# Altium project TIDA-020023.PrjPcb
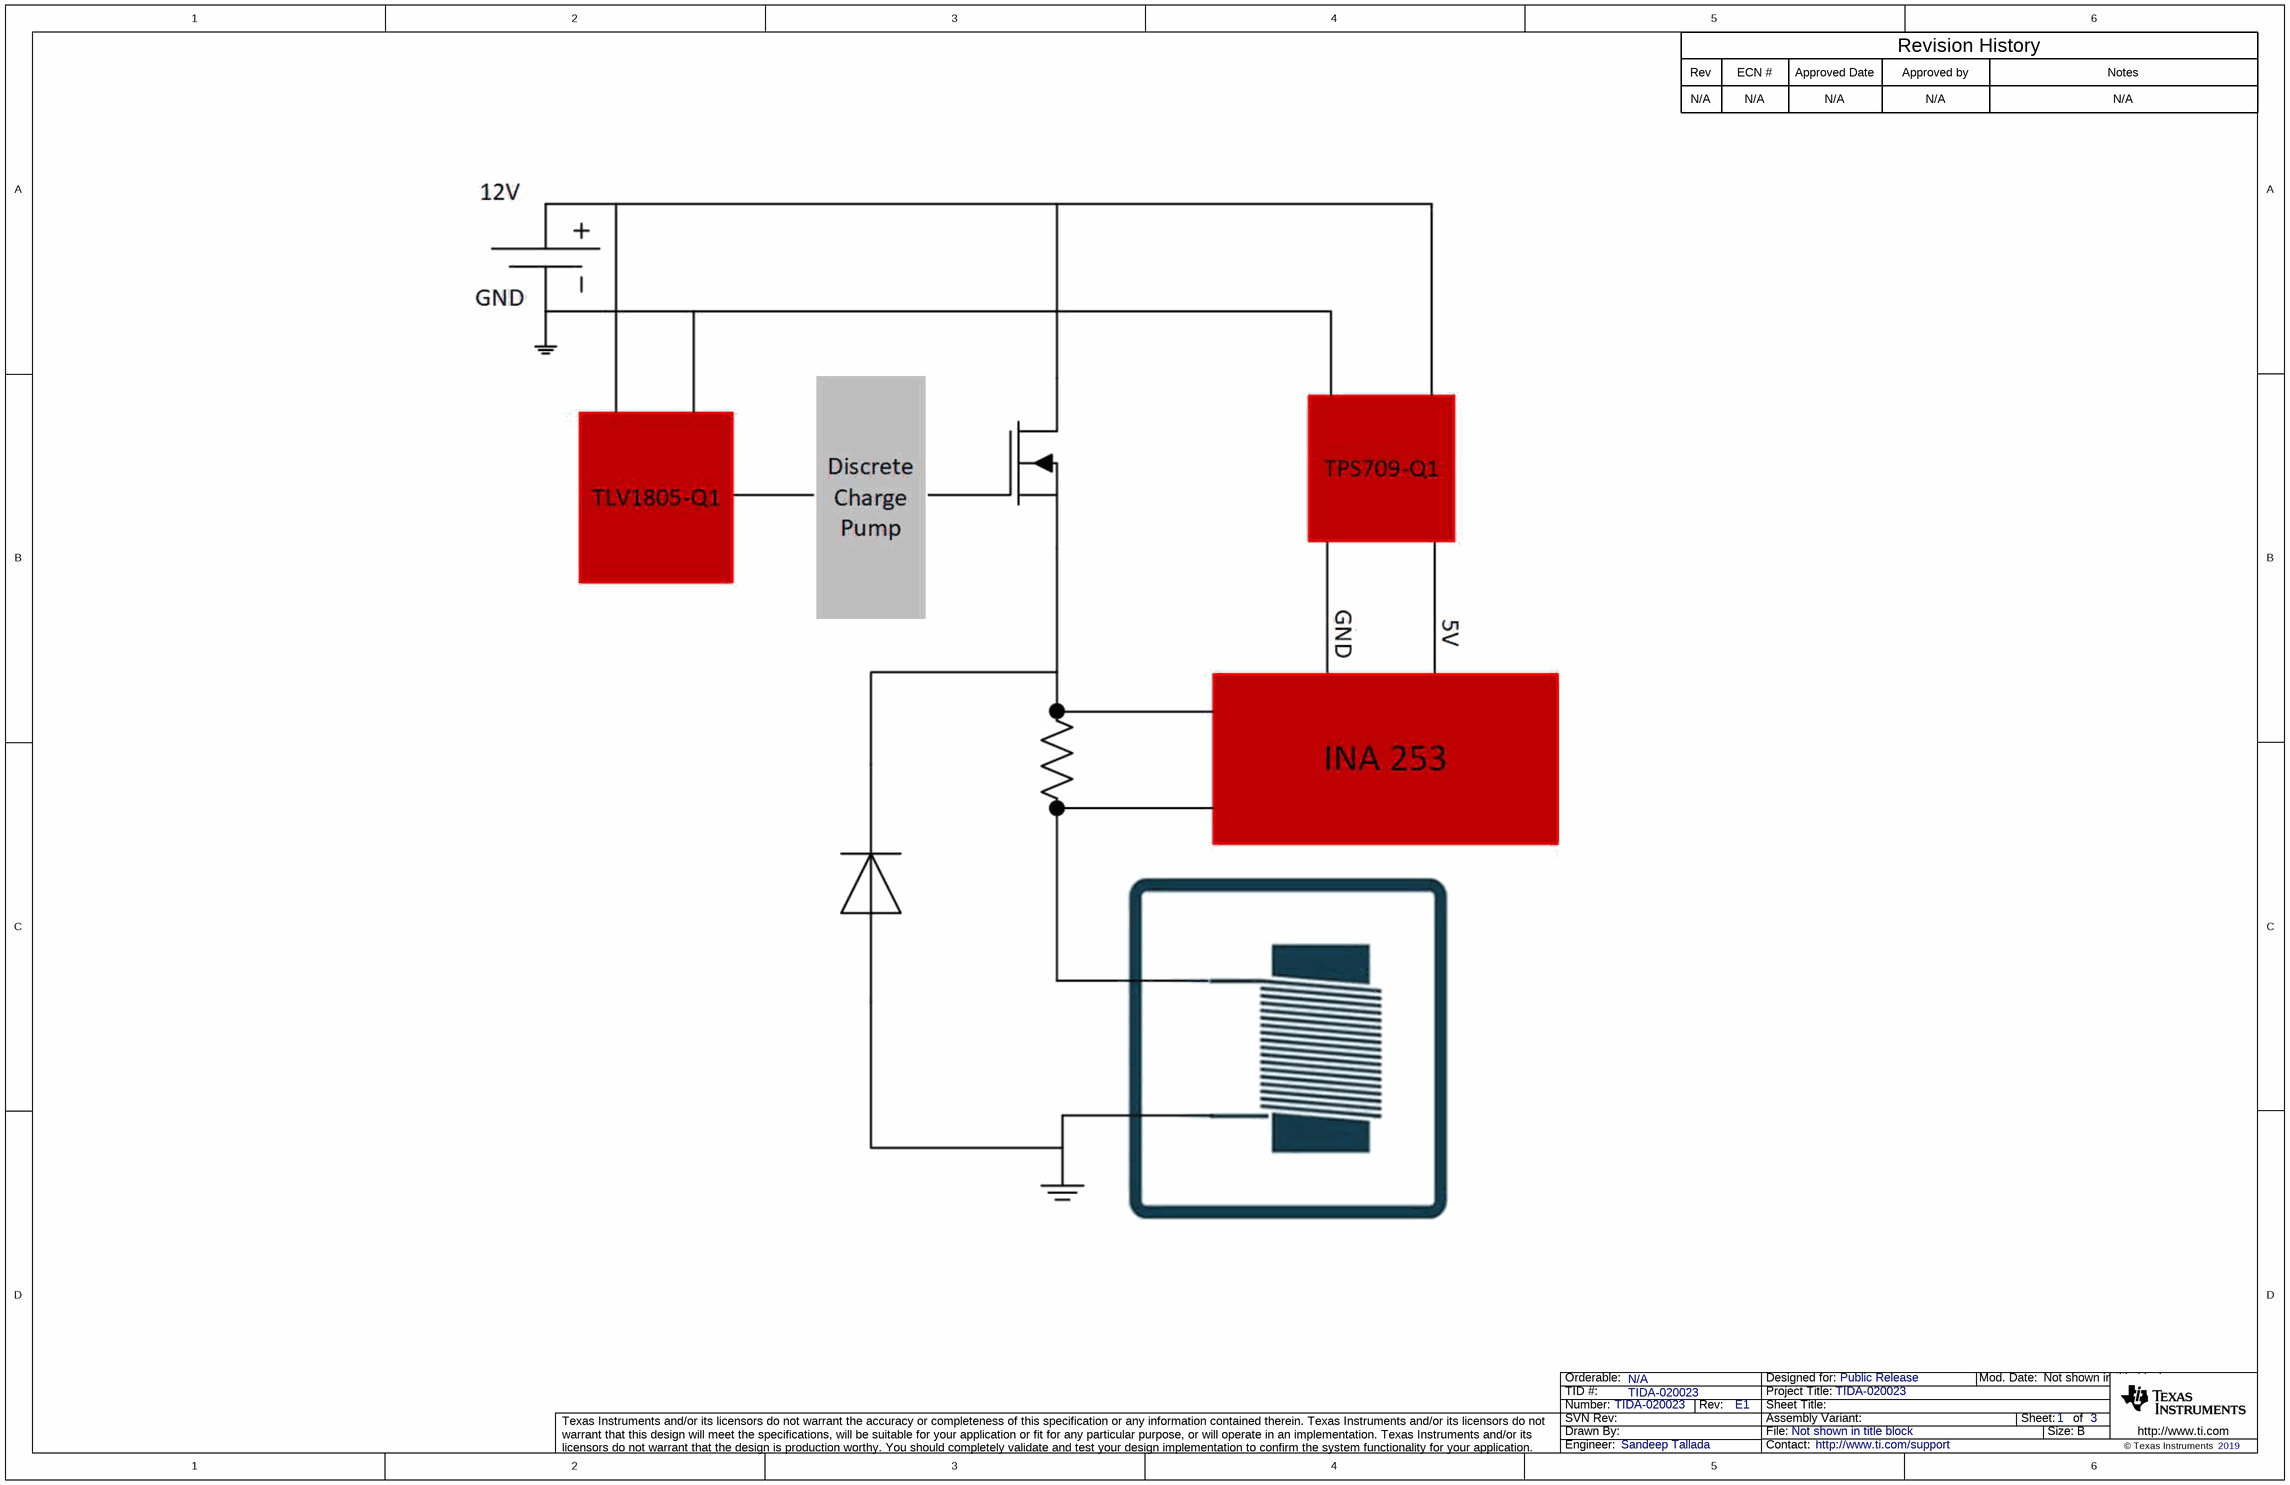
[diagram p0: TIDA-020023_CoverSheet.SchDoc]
CopyrightYear: 2019; EVM_orderable: N/A; PCB_Layout: Sandeep Tallada; PCB_Rev: E1; PRJ_Customer: Public Release; PRJ_Engineer: Sandeep Tallada; PRJ_Number: TIDA-020023; PRJ_Title: TIDA-020023; SCH_Rev: E1; TechSupport: http://www.ti.com/support; TID: TIDA-020023
3 sheets, 39 parts. Net scope: flat (ports and power ports of the same name join across sheets).
Board file: TIDA-020023_PCBLayout.PcbDoc
Sheets:
  TIDA-020023_CoverSheet.SchDoc
  TIDA-020023_Schematics.SchDoc
  TIDA-020023_EVM_Hardware.SchDoc

## Sheet TIDA-020023_CoverSheet.SchDoc
size 431 x 279 mm; Date: Not shown in title block; ApprovedBy: Not shown in title block; CheckedBy: Not shown in title block; Author: Not shown in title block; CompanyName: Not shown in title block; Engineer: Not shown in title block; Organization: Not shown in title block; Address1: Not shown in title block; Address2: Not shown in title block; Address3: Not shown in title block; Address4: Not shown in title block; DocumentNumber: 1; Revision: Use project parameter SCH_Rev; SheetNumber: 1; SheetTotal: 3; PageSetup: Record=PageOptions¦CenterHorizontal=True¦CenterVertical=True¦PrintScale=1.00¦XCorrection=1.00¦YCorrection=1.00¦PrintKind=0¦BorderSize=5000000¦LeftOffset=0¦BottomOffset=0¦Orientation=2¦PaperLength=1000¦PaperWidth=1000¦Scale=100¦PaperSource=15¦PrintQuality=600¦MediaType=1¦DitherType=10¦PaperKind=Letter¦PrintScaleMode=1

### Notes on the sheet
- Rev
- N/A
- ECN #
- Approved Date
- Approved by
- Revision History
- Notes

## Sheet TIDA-020023_Schematics.SchDoc
size 431 x 279 mm; Date: Not shown in title block; ApprovedBy: Not shown in title block; CheckedBy: Not shown in title block; Author: Not shown in title block; CompanyName: Not shown in title block; DrawnBy: Sandeep Tallada; Engineer: Sandeep Tallada; Organization: Not shown in title block; Address1: Not shown in title block; Address2: Not shown in title block; Address3: Not shown in title block; Address4: Not shown in title block; DocumentNumber: 1; Revision: Use project parameter SCH_Rev; SheetNumber: 2; SheetTotal: 3; PageSetup: Record=PageOptions¦CenterHorizontal=True¦CenterVertical=True¦PrintScale=0.62¦XCorrection=1.00¦YCorrection=1.00¦PrintKind=0¦BorderSize=5000000¦LeftOffset=0¦BottomOffset=0¦Orientation=2¦PaperLength=2794¦PaperWidth=2159¦Scale=100¦PaperSource=7¦PrintQuality=600¦MediaType=1¦DitherType=10¦PrintScaleMode=1¦PaperKind=8 1/2x11¦PaperIndex=1
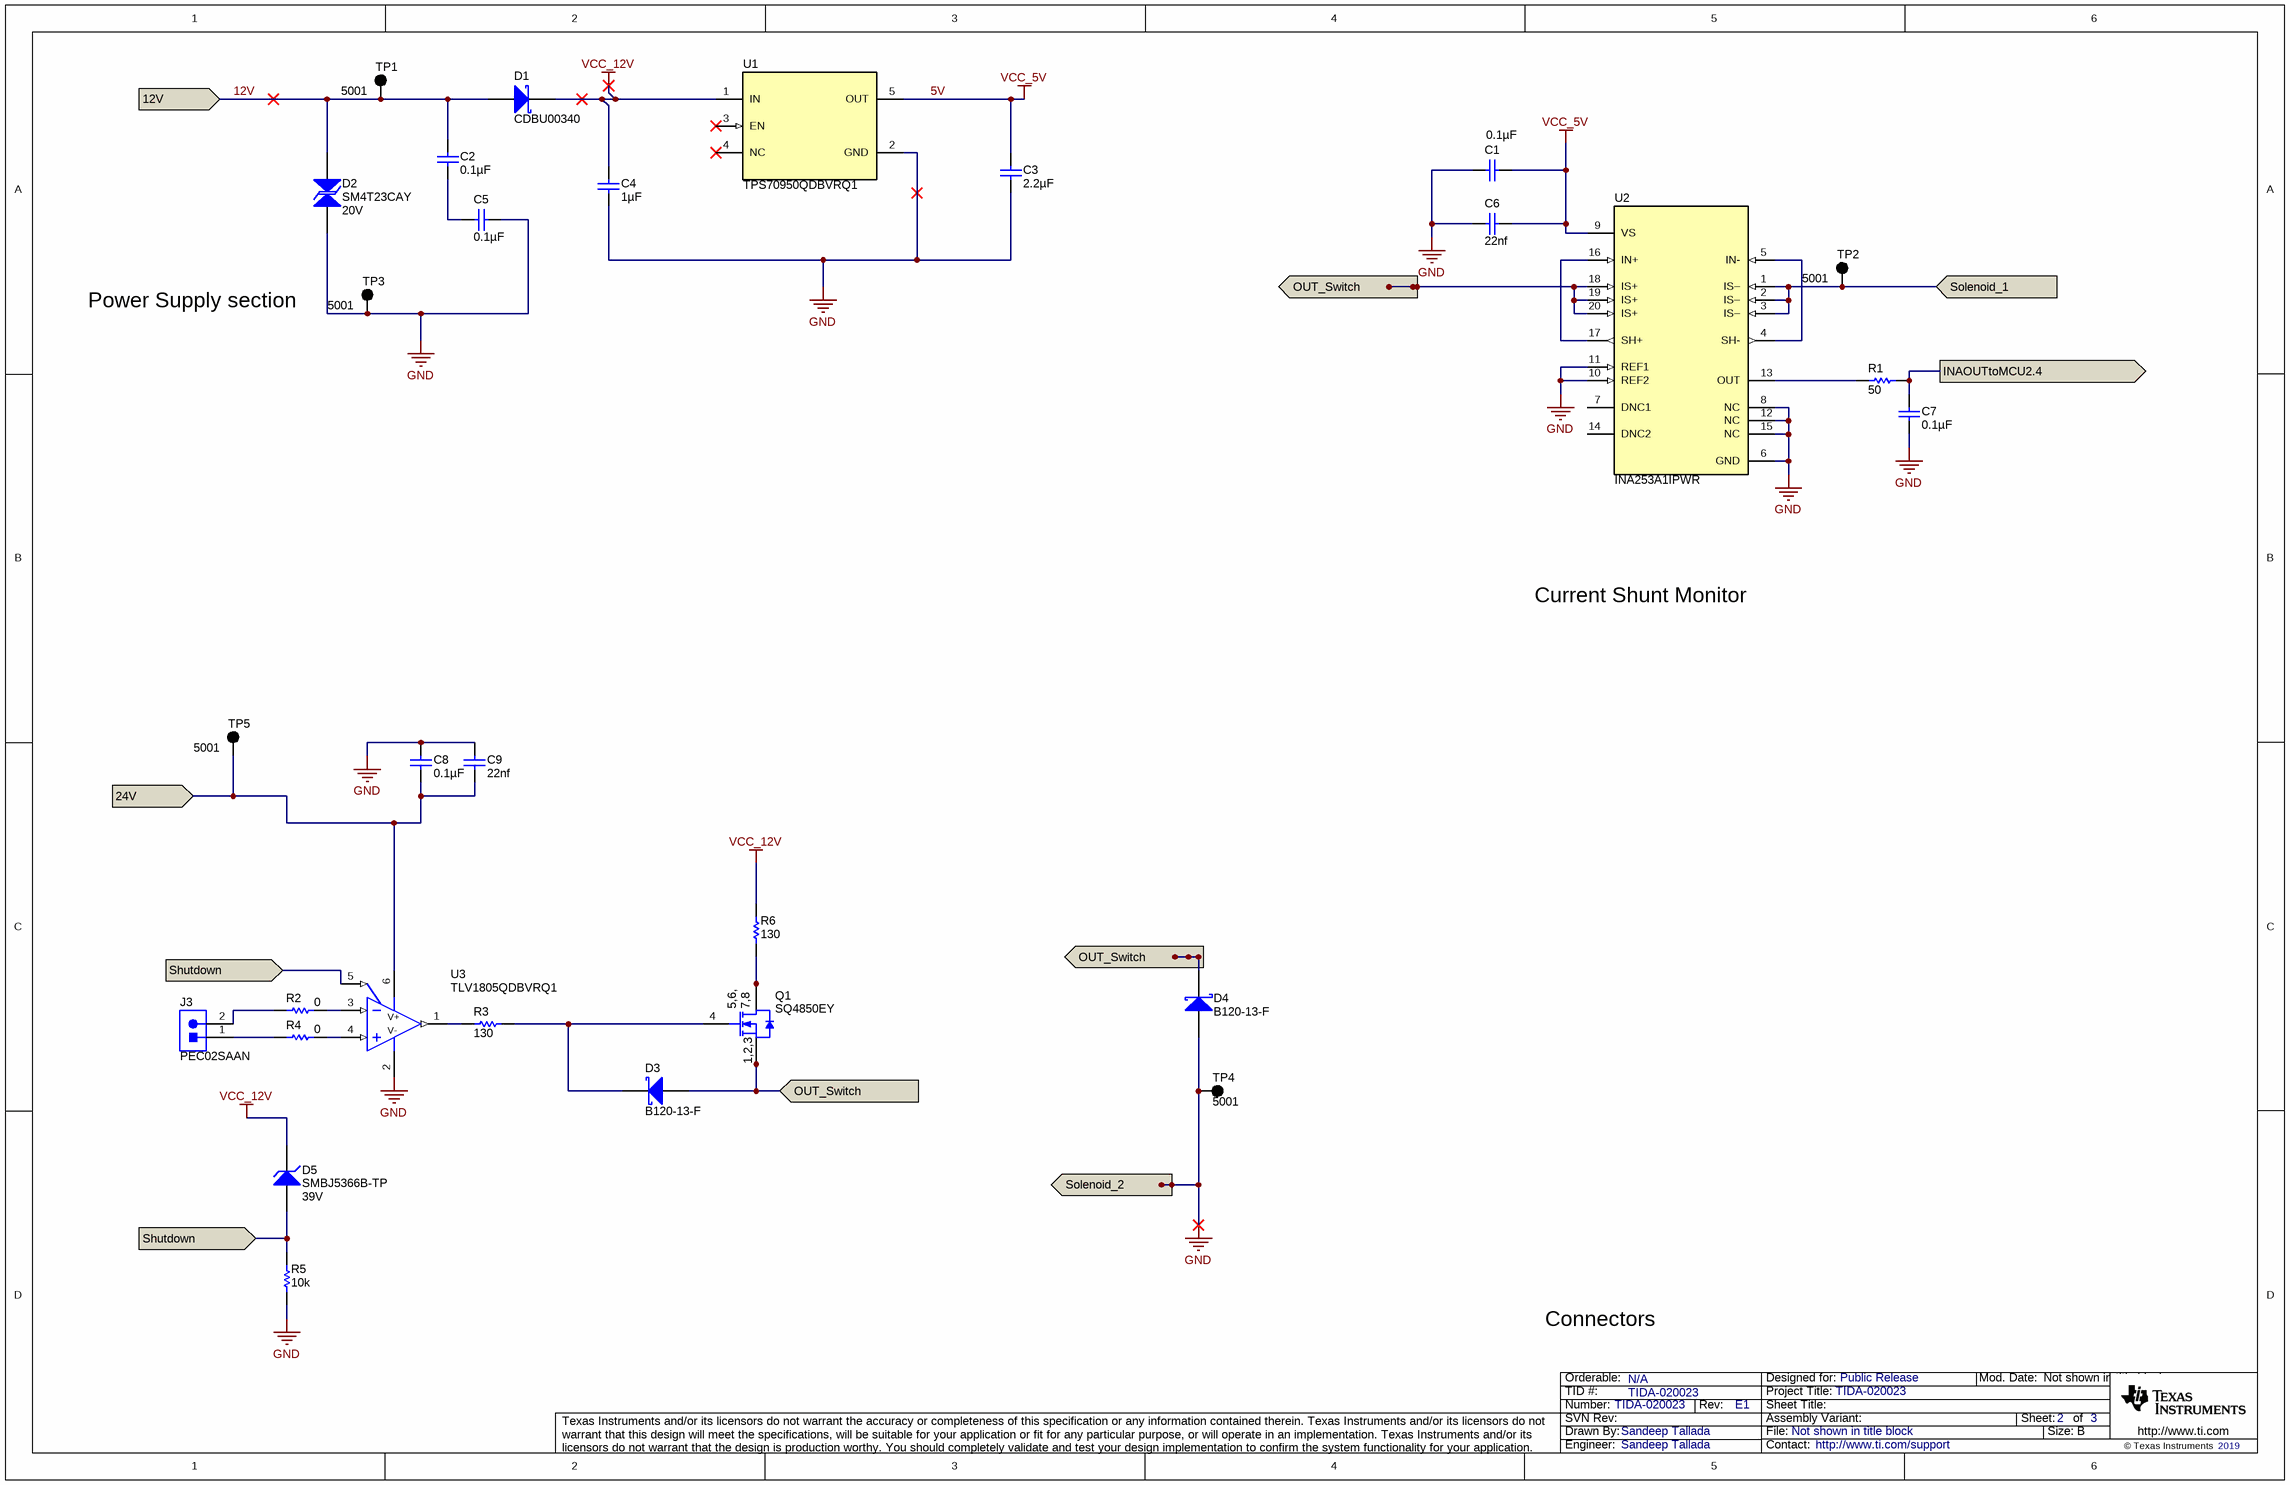
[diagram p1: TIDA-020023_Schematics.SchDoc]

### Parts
C1  ValueDisplayed: 0.1µF  [0603S]  (hidden comment: 0603YC104JAT2A)
C2  ValueDisplayed: 0.1µF  [0603S]  (hidden comment: GRM188R72A104KA35J)
C3  ValueDisplayed: 2.2µF  [0603S]  (hidden comment: GRM188Z71C225KE43)
C4  ValueDisplayed: 1µF  [0603S]  (hidden comment: CGA3E1X7R1V105K080AC)
C5  ValueDisplayed: 0.1µF  [0603S]  (hidden comment: GRM188R72A104KA35J)
C6  ValueDisplayed: 22nf  [0603S]  (hidden comment: CGA3E1X7R1V105K080AC)
C7  ValueDisplayed: 0.1µF  [0603S]  (hidden comment: 0603YC104JAT2A)
C8  ValueDisplayed: 0.1µF  [0603S]  (hidden comment: 0603YC104JAT2A)
C9  ValueDisplayed: 22nf  [0603S]  (hidden comment: CGA3E1X7R1V105K080AC)
D1  CDBU00340  [SOD-523F]
D2  SM4T23CAY  value 20V  [SMA_Bi]
D3  B120-13-F  [SMA]
D4  B120-13-F  [SMA]
D5  SMBJ5366B-TP  value 39V  [SMB]
J3  PEC02SAAN  [CONN_PEC02SAAN]
Q1  SQ4850EY  [SOIC-8]
R1  ValueDisplayed: 50  [0603S]  (hidden comment: FC0603E50R0BTBST1)
R2  ValueDisplayed: 0  [0402]  (hidden comment: CRCW04020000Z0EDHP)
R3  ValueDisplayed: 130  [0603]  (hidden comment: CRCW0603130RFKEA)
R4  ValueDisplayed: 0  [0402]  (hidden comment: CRCW04020000Z0EDHP)
R5  ValueDisplayed: 10k  [0603S]  (hidden comment: CRCW060310K0JNEA)
R6  ValueDisplayed: 130  [0603]  (hidden comment: CRCW0603130RFKEA)
TP1  5001  [Keystone5001]
TP2  5001  [Keystone5001]
TP3  5001  [Keystone5001]
TP4  5001  [Keystone5001]
TP5  5001  [Keystone5001]
U1  TPS70950QDBVRQ1  [DBV0005A_N]
U2  INA253A1IPWR  [PW0020A_N]
U3  TLV1805QDBVRQ1  [DBV0006A_N]

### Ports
12V (in), 24V (in), INAOUTtoMCU2.4 (out), OUT_Switch, Shutdown (in), Solenoid_1 (in), Solenoid_2 (in)

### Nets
5V: C1.2 C3.1 C6.2 U1.5(OUT) U2.9(VS)  [also labelled VCC_5V]
GND: C1.1 C3.2 C4.1 C5.2 C6.1 C7.2 C8.2 C9.2 D2.1 D4.2(A) R5.1 TP3.1 TP4.1 U1.2(GND) U2.6(GND) U2.8(NC) U2.10(REF2) U2.11(REF1) U2.12(NC) U2.15(NC) U3.2(V-) ; port Solenoid_2
VCC_12V: C4.2 D1.1(K) D5.1(K) R6.2 U1.1(IN)
12V: C2.1 D1.2(A) D2.2 TP1.1 ; port 12V
24V: C8.1 C9.1 TP5.1 U3.6(V+) ; port 24V
INAOUTtoMCU2.4: C7.1 R1.2 ; port INAOUTtoMCU2.4
OUT_Switch: D3.2(A) Q1.1(S) Q1.2(S) Q1.3(S) U2.18(IS+) U2.19(IS+) U2.20(IS+) ; port OUT_Switch
Shutdown: D5.2(A) R5.2 U3.5(SD) ; port Shutdown
Solenoid_1: TP2.1 U2.1(IS–) U2.2(IS–) U2.3(IS–) ; port Solenoid_1
NetC2_2: C2.2 C5.1
NetD3_1: D3.1(K) Q1.4(G) R3.2
NetJ3_1: J3.1 R4.1
NetJ3_2: J3.2 R2.1
NetQ1_5: Q1.5(D) Q1.6(D) Q1.7(D) Q1.8(D) R6.1
NetR1_1: R1.1 U2.13(OUT)
NetR2_2: R2.2 U3.3(IN-)
NetR3_1: R3.1 U3.1(OUT)
NetR4_2: R4.2 U3.4(IN+)
NetU2_4: U2.4(SH-) U2.5(IN-)
NetU2_16: U2.16(IN+) U2.17(SH+)

Not connected (* = marked no-connect by the designer): D4 1(K); U1 3(EN)* 4(NC)*; U2 7(DNC1) 14(DNC2)

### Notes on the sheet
- Power Supply section
- Current Shunt Monitor
- Connectors

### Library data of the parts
C1 C7 C8 = 0603YC104JAT2A: CAP, CERM, 0.1 µF, 16 V, +/- 5%, X7R, 0603; Manufacturer: AVX; Polarized: N; CompType: Capacitor; Value: 0.1uF; U/M: EA; Cap_F: 0.0000001; Tolerance_%: 5; ESR_ohm: 0.039; Value1: 0.039 ohm; VDC_V: 16; Value2: 16V; TaMin_C: -55; TaMax_C: 125; Cap_Case: 0603; AEC Category: Q200
C2 C5 = GRM188R72A104KA35J: CAP, CERM, 0.1 µF, 100 V, +/- 10%, X7R, 0603; Manufacturer: MuRata; Polarized: N; CompType: Capacitor; Value: 0.1uF; U/M: EA; Cap_F: 0.0000001; Tolerance_%: 10; Value1: Unknown; VDC_V: 100; Value2: 100V; TaMin_C: -55; TaMax_C: 125; Cap_Case: 0603; SizeArea_mm2: 1.28; SizeAreaWB_mm2: 4.68; SizeX_mm: 1.6; SizeY_mm: 0.8; SizeZ_mm: 1; AEC Category: Q200
C3 = GRM188Z71C225KE43: CAP, CERM, 2.2 µF, 16 V, +/- 10%, X7R, 0603; Manufacturer: MuRata; Polarized: N; CompType: Capacitor; Value: 2.2uF; U/M: EA; Cap_F: 0.0000022; Tolerance_%: 10; Value1: Unknown; VDC_V: 16; Value2: 16V; TaMin_C: -55; TaMax_C: 125; Cap_Case: 0603; AEC Category: Q200
C4 C6 C9 = CGA3E1X7R1V105K080AC: CAP, CERM, 1 µF, 35 V, +/- 10%, X7R, AEC-Q200 Grade 1, 0603; Manufacturer: TDK; Polarized: N; CompType: Capacitor; Value: 1uF; U/M: EA; Cap_F: 0.000001; Tolerance_%: 10; ESR_ohm: 0.005522; Value1: 0.005522 ohm; VDC_V: 35; Value2: 35V; IRMS_A: 2.21617; TaMin_C: -55; TaMax_C: 125; Cap_Case: 0603; SizeArea_mm2: 1.28; SizeAreaWB_mm2: 4.68; SizeX_mm: 1.6; SizeY_mm: 0.8; SizeZ_mm: 1; AEC Category: Q200; AEC Qualified: Y
D1 = CMP-0081923-2: Diode, Schottky, 45 V, 0.03 A, SOD-523F; Manufacturer: Comchip Technology; Io_A: 30mA; SizeX_mm: 1.7; SizeZ_mm: 0.85; SizeAreaWB_mm2: 5.13; Value2: 0.37V; AEC Category: Q101; Vf_V: 3.7dV; Value: 45V; AEC Qualified: N; Value1: 0.03A; TJmax_C: 125°C; SizeY_mm: 0.9; SizeArea_mm2: 1.53
D2 = CMP-0078854-3: Diode, TVS, Bi, 20 V, 42.8 Vc, AEC-Q101, SMA (non-polarized); Manufacturer: STMicroelectronics; Vbr_Min: 22.2V; SizeArea_mm2: 13.068125; Value1: 400W; AEC Qualified: Y; SizeY_mm: 2.575; SizeZ_mm: 2.65; Ipp: 54A; AEC Category: Q101; Vc: 42.8V; SizeAreaWB_mm2: 32.368125; Vbr_Max: 24.6V; SizeX_mm: 5.075
D3 D4 = CMP-0028374-2: Diode, Schottky, 20 V, 1 A, SMA; Manufacturer: Diodes Inc.; TJmax_C: 150°C; Value2: 0.5V; Green_Lifecycle: Active; SizeZ_mm: 2.87; Vr_V: 20V; Green_REACh: Passed; AEC Category: Q101; SizeX_mm: 5.59; SizeY_mm: 2.92; Value1: 1A; Vf_V: 5dV; SizeArea_mm2: 16.3228; RJC_CperW: 20; Value: 20V; SizeAreaWB_mm2: 37.3428
D5 = CMP-0005659-4: Diode, Zener, 39 V, 5 W, SMB; Manufacturer: Micro Commercial Components; SizeY_mm: 3.81; Power_W: 5W; SizeX_mm: 5.6; SizeZ_mm: 2.6; AEC Category: Q101; SizeAreaWB_mm2: 44.156; SizeArea_mm2: 21.336; RJA_CperW: 226
J3 = CMP-0002337-1: Header, 100mil, 2x1, Tin, TH; Manufacturer: Sullins Connector Solutions; CNHeader: TRUE; Current_A: 3A; Green_Lifecycle: Not Set; Shrouded: N; Gender: Male; Green_REACh: Incomplete; Voltage_V: 1.8kV; Row_Count: 1; Pitch_mm: 2.54; CT: FALSE; Cert_UL: Y
Q1 = CMP-0000872-1: MOSFET, N-CH, 60 V, 12 A, SOIC-8; Alternate Manufacturer: None; Manufacturer: Vishay-Siliconix; SizeZ_mm: 1.75; ChType: N; Value2: 20 nC; Value1: 0.03; VdsMax_V: 60V; SizeX_mm: 5.99; SizeY_mm: 4.9; Vgs_V: 20V; Value: 60V; Rdson45_ohm: 0.031; SizeArea_mm2: 29.351; AEC Category: Q101; IdsMax_A: 12A; SizeAreaWB_mm2: 55.131; U/M: EA; QgTyp_nC: 20
R1 = FC0603E50R0BTBST1: RES, 50, 0.1%, 0.125 W, 0603; Manufacturer: Vishay Thin Film; CompType: Resistor; Value: 50; Value_Code: 50R0; Tolerance_%: 0.1; Power_W: 0.125; Value2: 0.125W; TempCo: 25 ppm/C; SizeArea_mm2: 1.28; SizeX_mm: 1.6; SizeY_mm: 0.8; SizeZ_mm: 1; U/M: EA; AEC Category: Q200; AEC Qualified: N
R2 R4 = CMP-0081856-1: RES, 0, 0%, 0.2 W, AEC-Q200 Grade 0, 0402; Manufacturer: Vishay-Dale; SizeAreaWB_mm2: 3; SizeArea_mm2: 0.5; AEC Qualified: Y; AEC Category: Q200; Value: 0; SizeZ_mm: 0.6; Power_W: 200mW; VDC_V: 50V; Value2: 0.2W; SizeX_mm: 1
R3 = CMP-0022037-5: RES, 130, 1%, 0.1 W, AEC-Q200 Grade 0, 0603; Manufacturer: Vishay-Dale; Power_W: 100mW; TempCo: 100 ppm/C; Value_Code: 130R; Value: 130; EIA_Code: E96; SizeX_mm: 1.6; SizeY_mm: 0.8; SizeZ_mm: 1; Value2: 0.1W; SizeArea_mm2: 1.28; AEC Qualified: Y; VDC_V: 75V; AEC Category: Q200; AEC Grade: 0
R5 = CRCW060310K0JNEA: RES, 10 k, 5%, 0.1 W, 0603; Manufacturer: Vishay-Dale; CompType: Resistor; Value: 10k; Res_ohm: 10000; Value_Code: 10k0; Tolerance_%: 5; Power_W: 0.1; Value2: 0.1W; VDC_V: 75; TempCo: 200 ppm/C; SizeArea_mm2: 1.28; SizeX_mm: 1.6; SizeY_mm: 0.8; SizeZ_mm: 1; EIA_Code: E24; U/M: EA; AEC Category: Q200
R6 = CMP-0022037-5: RES, 130, 1%, 0.1 W, AEC-Q200 Grade 0, 0603; Manufacturer: Vishay-Dale; Power_W: 100mW; TempCo: 100 ppm/C; Value_Code: 130R; Value: 130; EIA_Code: E96; SizeX_mm: 1.6; SizeY_mm: 0.8; SizeZ_mm: 1; Value2: 0.1W; SizeArea_mm2: 1.28; CompType: Resistor; AEC Qualified: Y; VDC_V: 75V; AEC Category: Q200; AEC Grade: 0
TP1-TP5 = CMP-0055138-1: Test Point, Miniature, Black, TH; Manufacturer: Keystone; CNHeader: FALSE; Green_Lifecycle: Active; Green_REACh: Passed; ContactFinish: Silver; CT: TRUE
U1 = CMP-0079136-1: 150-mA, 30-V, Ultra-Low IQ, Wide Input LDO with Reverse Current Protection for Automotive, DBV0005A (SOT-23-5); Alternate Manufacturer: Texas Instruments; SizeAreaWB_mm2: 14.82; SizeZ_mm: 1.45; SizeX_mm: 2.8; SizeY_mm: 2.9; SizeArea_mm2: 8.12; CompType: IC; AEC Qualified: Y; AEC Category: Q200
U2 = INA253A1IPWR: Low- or High-Side, Bidirectional, Zero-Drift, Current-Shunt Monitor with Integrated Precision Low Inductive Shunt Resistor, PW0020A (TSSOP-20); Manufacturer: Texas Instruments; SymbolCreator: Altium; SizeArea_mm2: 43.56; SizeAreaWB_mm2: 73.96; SizeX_mm: 6.6; SizeZ_mm: 1.2; CompType: IC; U/M: EA
U3 = CMP-0080758-2: Automotive 40-V, microPower, Push-Pull Comparator with Shutdown, DBV0006A (SOT-23-6); Alternate Manufacturer: Texas Instruments; SizeAreaWB_mm2: 14.82; SizeZ_mm: 1.45; SizeX_mm: 2.8; SizeY_mm: 2.9; SizeArea_mm2: 8.12; CompType: IC; AEC Qualified: Y; AEC Category: Q200

## Sheet TIDA-020023_EVM_Hardware.SchDoc
size 431 x 279 mm; Date: Not shown in title block; ApprovedBy: Not shown in title block; CheckedBy: Not shown in title block; Author: Not shown in title block; CompanyName: Not shown in title block; Engineer: Not shown in title block; Organization: Not shown in title block; Address1: Not shown in title block; Address2: Not shown in title block; Address3: Not shown in title block; Address4: Not shown in title block; DocumentNumber: 1; Revision: Use project parameter SCH_Rev; SheetNumber: 3; SheetTotal: 3; PageSetup: Record=PageOptions¦CenterHorizontal=True¦CenterVertical=True¦PrintScale=1.00¦XCorrection=1.00¦YCorrection=1.00¦PrintKind=0¦BorderSize=5000000¦LeftOffset=0¦BottomOffset=0¦Orientation=2¦PaperLength=1000¦PaperWidth=1000¦Scale=100¦PaperSource=15¦PrintQuality=600¦MediaType=1¦DitherType=10¦PaperKind=Letter¦PrintScaleMode=1
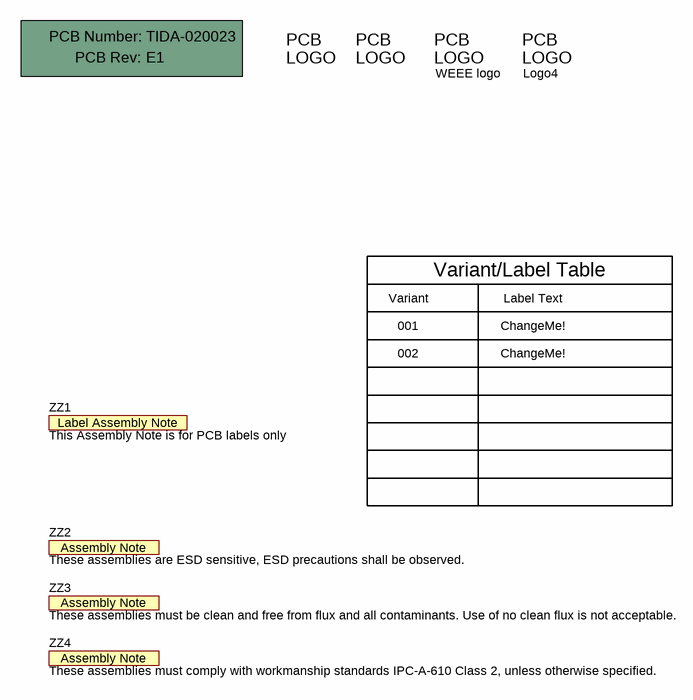
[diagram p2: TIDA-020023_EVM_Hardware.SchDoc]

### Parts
!PCB1  Printed Circuit Board  (value not drawn)  (mechanical)
Logo1  WEEE logo  [WEEE_Minimum]  (no BOM)
Logo2  Pb-Free Symbol  [Pb-Free_Overlay_Small]  (value not drawn)  (no BOM)
Logo3  FCC disclaimer  [FCC_disclaimer]  (value not drawn)  (no BOM)
Logo4  ESD Susceptible  [ESD_Overlay_Medium]  (value not drawn)  (no BOM)
ZZ1  This Assembly Note is for PCB labels only  [AssemblyNoteLabel]  (no BOM)
ZZ2  These assemblies are ESD sensitive, ESD precautions shall be observed.  [AssemblyNote]  (no BOM)
ZZ3  These assemblies must be clean and free from flux and all contaminants. Use of no clean flux is not acceptable.  [AssemblyNote]  (no BOM)
ZZ4  These assemblies must comply with workmanship standards IPC-A-610 Class 2, unless otherwise specified.  [AssemblyNote]  (no BOM)

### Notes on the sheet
- Variant
- Variant/Label Table
- Label Text
- 001
- 002
- ChangeMe!

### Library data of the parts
!PCB1 = PCB: Manufacturer: Any; PartNumber: TIDA-020023; SymbolCreator: a0412235
Logo1 = CMP-0074769-1
Logo2 = Pb-Free: SymbolCreator: a0412235
Logo3 = FCC_disclaimer: SymbolCreator: a0412235
Logo4 = ESD_Susceptible: ESD Susceptible Symbol; SymbolCreator: a0412235
ZZ1 = AssemblyNoteLabel: SymbolCreator: a0412235
ZZ2-ZZ4 = AssemblyNote: SymbolCreator: codlsc

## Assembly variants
001: not fitted FID1 FID2 FID3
